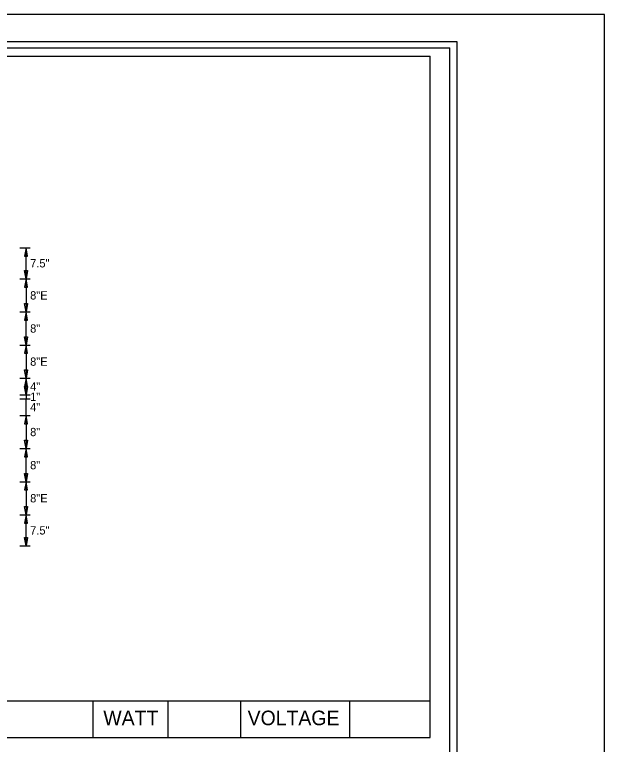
# Model space of a CAD drawing. Extents: x 1274.1 to 1363.1, y 833.5 to 890.6.
# Drawn here: x 1351.23 to 1363.1, y 875.95 to 890.63 of the extents above; entities that cross this region are included whole.
import ezdxf

# ---------------------------------------------------------------- set-up
doc = ezdxf.new("R2010")
doc.units = 0
for name, color, linetype in [('GSDims', 7, 'Continuous'), ('PlotBorder_dp', 7, 'Continuous'), ('SheetBorder_dp', 7, 'Continuous'), ('SheetLinesMisc2_dp', 7, 'Continuous'), ('TextMinor', 7, 'Continuous')]:
    doc.layers.add(name, color=color, linetype=linetype)

msp = doc.modelspace()

# ---------------------------------------------------------------- linework, layer by layer
at = {"layer": 'GSDims'}
for p, q in [((1351.339, 885.942), (1351.547, 885.942)), ((1351.339, 885.942), (1351.339, 885.942)), ((1351.464, 885.317), (1351.464, 885.942)), ((1351.339, 885.317), (1351.547, 885.317)), ((1351.339, 885.317), (1351.547, 885.317)), ((1351.464, 885.317), (1351.464, 884.65)), ((1351.339, 884.65), (1351.547, 884.65)), ((1351.339, 884.65), (1351.547, 884.65)), ((1351.464, 883.984), (1351.464, 884.65)), ((1351.339, 883.984), (1351.547, 883.984)), ((1351.339, 883.984), (1351.547, 883.984)), ((1351.464, 883.984), (1351.464, 883.317)), ((1351.339, 883.317), (1351.547, 883.317)), ((1351.339, 883.317), (1351.547, 883.317)), ((1351.464, 882.984), (1351.464, 883.317)), ((1351.339, 882.984), (1351.547, 882.984)), ((1351.339, 882.984), (1351.547, 882.984)), ((1351.464, 882.984), (1351.464, 882.9)), ((1351.339, 882.9), (1351.547, 882.9)), ((1351.339, 882.9), (1351.547, 882.9)), ((1351.464, 882.567), (1351.464, 882.9)), ((1351.339, 882.567), (1351.547, 882.567)), ((1351.339, 882.567), (1351.547, 882.567)), ((1351.464, 882.567), (1351.464, 881.9)), ((1351.339, 881.9), (1351.547, 881.9)), ((1351.339, 881.9), (1351.547, 881.9)), ((1351.464, 881.234), (1351.464, 881.9)), ((1351.339, 881.234), (1351.547, 881.234)), ((1351.339, 881.234), (1351.547, 881.234)), ((1351.464, 881.234), (1351.464, 880.567)), ((1351.339, 880.567), (1351.547, 880.567)), ((1351.339, 880.567), (1351.547, 880.567)), ((1351.464, 879.942), (1351.464, 880.567)), ((1351.339, 879.942), (1351.547, 879.942)), ((1351.339, 879.942), (1351.339, 879.942))]:
    msp.add_line(p, q, dxfattribs=at)
for points in [[(1351.464, 885.942), (1351.436, 885.775), (1351.491, 885.775)], [(1351.464, 885.317), (1351.436, 885.484), (1351.491, 885.484)], [(1351.464, 885.317), (1351.436, 885.15), (1351.491, 885.15)], [(1351.464, 884.65), (1351.436, 884.817), (1351.491, 884.817)], [(1351.464, 884.65), (1351.436, 884.484), (1351.491, 884.484)], [(1351.464, 883.984), (1351.436, 884.15), (1351.491, 884.15)], [(1351.464, 883.984), (1351.436, 883.817), (1351.491, 883.817)], [(1351.464, 883.317), (1351.436, 883.484), (1351.491, 883.484)], [(1351.464, 883.317), (1351.436, 883.15), (1351.491, 883.15)], [(1351.464, 882.984), (1351.436, 883.15), (1351.491, 883.15)], [(1351.464, 882.567), (1351.436, 882.4), (1351.491, 882.4)], [(1351.464, 881.9), (1351.436, 882.067), (1351.491, 882.067)], [(1351.464, 881.9), (1351.436, 881.734), (1351.491, 881.734)], [(1351.464, 881.234), (1351.436, 881.4), (1351.491, 881.4)], [(1351.464, 881.234), (1351.436, 881.067), (1351.491, 881.067)], [(1351.464, 880.567), (1351.436, 880.734), (1351.491, 880.734)], [(1351.464, 880.567), (1351.436, 880.4), (1351.491, 880.4)], [(1351.464, 879.942), (1351.436, 880.109), (1351.491, 880.109)]]:
    msp.add_lwpolyline(points, close=True, dxfattribs=at)
at = {"layer": 'PlotBorder_dp'}
msp.add_lwpolyline([(1274.135, 833.481), (1363.097, 833.481), (1363.097, 890.634), (1274.135, 890.634)], close=True, dxfattribs=at)
at = {"layer": 'SheetBorder_dp'}
for p, q in [((1277.101, 890.095), (1360.132, 890.095)), ((1360.132, 890.095), (1360.132, 834.02))]:
    msp.add_line(p, q, dxfattribs=at)
at = {"layer": 'SheetLinesMisc2_dp'}
for p, q in [((1277.247, 889.967), (1359.988, 889.967)), ((1359.988, 838.462), (1359.988, 889.967)), ((1331.451, 889.796), (1359.592, 889.796)), ((1359.592, 876.088), (1359.592, 889.796)), ((1331.451, 876.823), (1359.592, 876.823)), ((1352.81, 876.823), (1352.81, 876.088)), ((1354.319, 876.823), (1354.319, 876.088)), ((1355.775, 876.823), (1355.775, 876.088)), ((1357.967, 876.823), (1357.967, 876.088)), ((1331.451, 876.088), (1359.592, 876.088))]:
    msp.add_line(p, q, dxfattribs=at)

# ---------------------------------------------------------------- texts
at = {"layer": 'GSDims'}
for s, p in [('7.5"', (1351.547, 885.546)), ('8"E', (1351.547, 884.9)), ('8"', (1351.547, 884.234)), ('8"E', (1351.547, 883.567)), ('4"', (1351.547, 883.067)), ('1"', (1351.547, 882.859)), ('4"', (1351.547, 882.65)), ('8"', (1351.547, 882.15)), ('8"', (1351.547, 881.484)), ('8"E', (1351.547, 880.817)), ('7.5"', (1351.547, 880.171))]:
    msp.add_text(s, height=0.1667, dxfattribs=at).set_placement(p)
at = {"layer": 'TextMinor'}
for s, p in [('WATT', (1353.019, 876.334)), ('VOLTAGE', (1355.921, 876.334))]:
    msp.add_text(s, height=0.2923, dxfattribs=at).set_placement(p)

doc.saveas('drawing.dxf')
